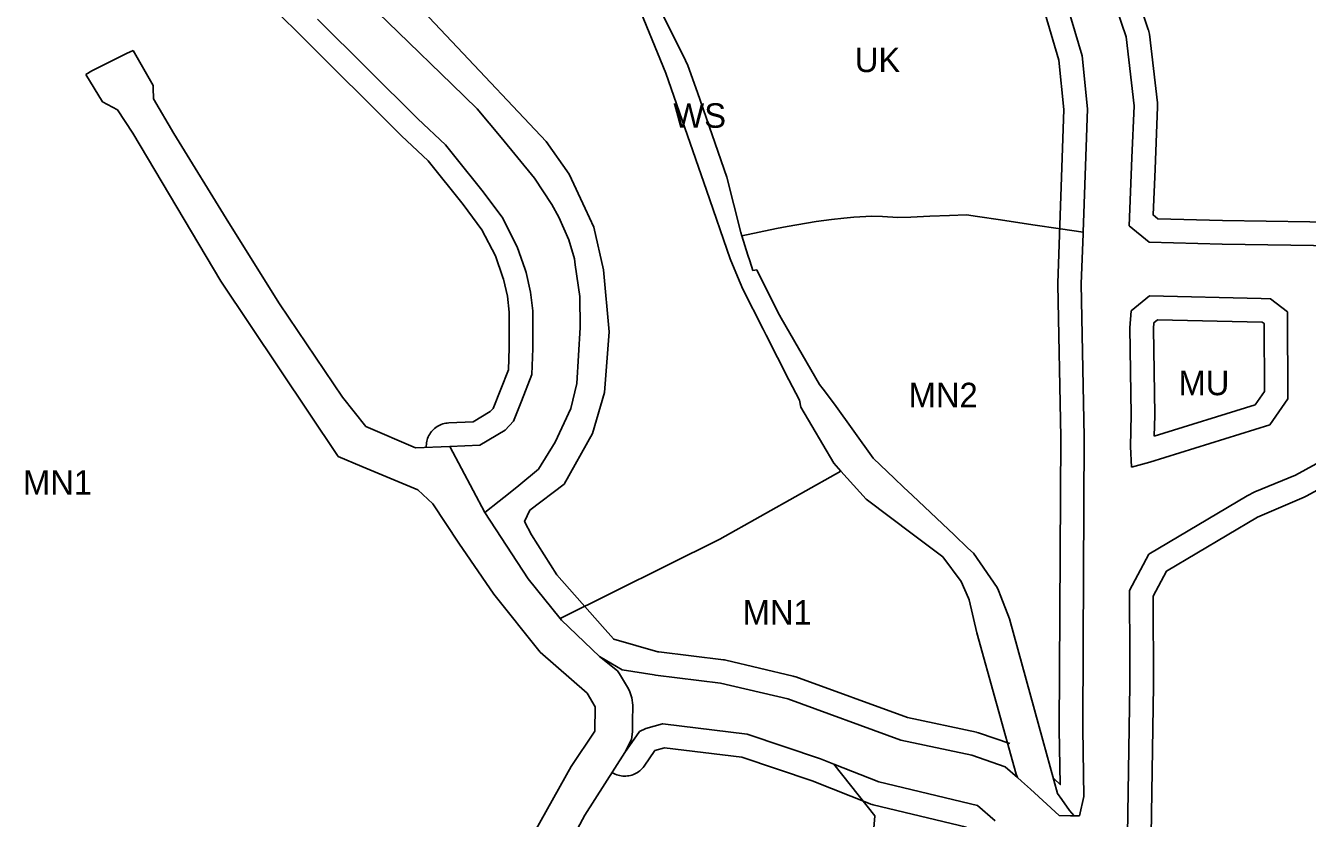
# Model space of a CAD drawing. Extents: x 7435758 to 7439981, y 5550649 to 5554049.
# Drawn here: x 7437108.7 to 7437381.1, y 5551668.8 to 5551837.1 of the extents above; entities that cross this region are included whole.
import ezdxf

# ---------------------------------------------------------------- set-up
doc = ezdxf.new("R2010")
doc.units = 0
for name, color, linetype in [('linie_rozgraniczające', 7, 'Continuous'), ('linie_zabudowy_nieprzekraczalne', 7, 'Continuous'), ('oznaczenia_przeznaczen', 7, 'Continuous')]:
    doc.layers.add(name, color=color, linetype=linetype)

msp = doc.modelspace()

# ---------------------------------------------------------------- linework, layer by layer
at = {"layer": 'linie_rozgraniczające'}
for p, q in [((7437342.53, 5551834.72), (7437337.64, 5551849.43)), ((7437238.33, 5551842.82), (7437244.76, 5551827.03)), ((7437248.93, 5551829.73), (7437241.63, 5551844.38)), ((7437187.89, 5551835.71), (7437181.49, 5551841.92)), ((7437330.07, 5551841.21), (7437333.2, 5551830.73)), ((7437170.79, 5551838.52), (7437192.04, 5551817.35)), ((7437199.27, 5551824.66), (7437187.89, 5551835.71)), ((7437344.25, 5551820.11), (7437342.53, 5551834.72)), ((7437130.2, 5551831.19), (7437122.83, 5551827.52)), ((7437131.58, 5551831.83), (7437130.2, 5551831.19)), ((7437135.84, 5551824.4), (7437131.58, 5551831.83)), ((7437249.47, 5551828.65), (7437248.93, 5551829.73)), ((7437251.48, 5551822.89), (7437249.47, 5551828.65)), ((7437333.2, 5551830.73), (7437334.34, 5551819.48)), ((7437122.83, 5551827.52), (7437121.57, 5551826.75)), ((7437121.57, 5551826.75), (7437125.09, 5551820.97)), ((7437244.76, 5551827.03), (7437253.4, 5551802.16)), ((7437135.85, 5551823.92), (7437135.84, 5551824.4)), ((7437135.91, 5551821.54), (7437135.85, 5551823.92)), ((7437204.65, 5551819.43), (7437199.27, 5551824.66)), ((7437125.09, 5551820.97), (7437128.27, 5551819.24)), ((7437140.23, 5551814.22), (7437135.91, 5551821.54)), ((7437257.73, 5551804.97), (7437251.48, 5551822.89)), ((7437128.27, 5551819.24), (7437131.54, 5551814.26)), ((7437209.79, 5551813.35), (7437204.65, 5551819.43)), ((7437334.34, 5551819.48), (7437333.98, 5551809.36)), ((7437343.79, 5551809.08), (7437344.25, 5551820.11)), ((7437192.04, 5551817.35), (7437197.92, 5551811.81)), ((7437131.54, 5551814.26), (7437150.19, 5551782.86)), ((7437151.89, 5551795.25), (7437140.23, 5551814.22)), ((7437216.85, 5551804.72), (7437209.79, 5551813.35)), ((7437197.92, 5551811.81), (7437200.23, 5551808.94)), ((7437333.98, 5551809.36), (7437333.41, 5551793.26)), ((7437200.23, 5551808.94), (7437205.65, 5551802.2)), ((7437343.19, 5551794.6), (7437343.79, 5551809.08)), ((7437220.51, 5551799.11), (7437216.85, 5551804.72)), ((7437260.73, 5551793.18), (7437257.73, 5551804.97)), ((7437205.65, 5551802.2), (7437209.96, 5551796.43)), ((7437253.4, 5551802.16), (7437258.46, 5551787.58)), ((7437222.04, 5551796.45), (7437220.51, 5551799.11)), ((7437209.96, 5551796.43), (7437213.16, 5551790.18)), ((7437224.17, 5551791.6), (7437222.04, 5551796.45)), ((7437279.95, 5551795.97), (7437276.72, 5551795.5)), ((7437282.57, 5551796.22), (7437279.95, 5551795.97)), ((7437284.72, 5551796.42), (7437282.57, 5551796.22)), ((7437288.52, 5551796.69), (7437284.72, 5551796.42)), ((7437290.81, 5551796.62), (7437288.52, 5551796.69)), ((7437294.07, 5551796.37), (7437290.81, 5551796.62)), ((7437296.8, 5551796.48), (7437294.07, 5551796.37)), ((7437300.84, 5551796.65), (7437296.8, 5551796.48)), ((7437305.05, 5551796.82), (7437300.84, 5551796.65)), ((7437308.64, 5551796.97), (7437305.05, 5551796.82)), ((7437311.01, 5551796.61), (7437308.64, 5551796.97)), ((7437315.87, 5551795.89), (7437311.01, 5551796.61)), ((7437322.76, 5551794.85), (7437315.87, 5551795.89)), ((7437162.7, 5551778.05), (7437151.89, 5551795.25)), ((7437260.91, 5551792.5), (7437260.73, 5551793.18)), ((7437268.28, 5551794.06), (7437260.91, 5551792.5)), ((7437270.56, 5551794.45), (7437268.28, 5551794.06)), ((7437276.72, 5551795.5), (7437270.56, 5551794.45)), ((7437328.64, 5551793.97), (7437322.76, 5551794.85)), ((7437333.41, 5551793.26), (7437328.64, 5551793.97)), ((7437333.41, 5551793.26), (7437333.4, 5551792.92)), ((7437347.45, 5551791.15), (7437343.19, 5551794.6)), ((7437225.33, 5551787.62), (7437224.17, 5551791.6)), ((7437262.2, 5551788.39), (7437260.91, 5551792.5)), ((7437333.4, 5551792.92), (7437333.02, 5551782.27)), ((7437362.95, 5551790.73), (7437347.45, 5551791.15)), ((7437391.92, 5551790.26), (7437362.95, 5551790.73)), ((7437213.16, 5551790.18), (7437214.87, 5551785.32)), ((7437225.51, 5551786.35), (7437225.33, 5551787.62)), ((7437258.46, 5551787.58), (7437260.02, 5551783.82)), ((7437262.58, 5551787.16), (7437262.2, 5551788.39)), ((7437214.87, 5551785.32), (7437215.1, 5551784.68)), ((7437226.5, 5551779.6), (7437225.51, 5551786.35)), ((7437263.23, 5551785.09), (7437262.58, 5551787.16)), ((7437264.08, 5551785.25), (7437263.23, 5551785.09)), ((7437268.65, 5551776.1), (7437264.08, 5551785.25)), ((7437150.19, 5551782.86), (7437175.17, 5551745.63)), ((7437215.1, 5551784.68), (7437216.03, 5551780.49)), ((7437260.02, 5551783.82), (7437261.13, 5551781.16)), ((7437333.02, 5551782.27), (7437333.66, 5551749.77)), ((7437216.03, 5551780.49), (7437216.48, 5551776.54)), ((7437226.57, 5551772.99), (7437226.5, 5551779.6)), ((7437261.13, 5551781.16), (7437265.41, 5551772.68)), ((7437343.65, 5551776.57), (7437347.49, 5551779.72)), ((7437347.49, 5551779.72), (7437371.21, 5551779.19)), ((7437176.08, 5551758.24), (7437162.7, 5551778.05)), ((7437371.21, 5551779.19), (7437373.26, 5551779.12)), ((7437373.26, 5551779.12), (7437376.85, 5551776.36)), ((7437216.48, 5551776.54), (7437216.48, 5551768.59)), ((7437268.92, 5551775.64), (7437268.65, 5551776.1)), ((7437269.29, 5551774.98), (7437268.92, 5551775.64)), ((7437277.44, 5551760.89), (7437269.29, 5551774.98)), ((7437343.34, 5551772.98), (7437343.65, 5551776.57)), ((7437376.85, 5551776.36), (7437376.93, 5551757.87)), ((7437225.88, 5551761.1), (7437226.57, 5551772.99)), ((7437265.41, 5551772.68), (7437266.06, 5551771.41)), ((7437266.06, 5551771.41), (7437270.88, 5551761.88)), ((7437343.64, 5551754.47), (7437343.34, 5551772.98)), ((7437216.48, 5551768.59), (7437216.29, 5551763.03)), ((7437216.29, 5551763.03), (7437214.07, 5551757.39)), ((7437224.57, 5551755.83), (7437225.88, 5551761.1)), ((7437270.88, 5551761.88), (7437273.13, 5551757.57)), ((7437278.17, 5551759.94), (7437277.44, 5551760.89)), ((7437181, 5551751.96), (7437176.08, 5551758.24)), ((7437280.58, 5551756.75), (7437278.17, 5551759.94)), ((7437376.93, 5551757.87), (7437373.07, 5551752.36)), ((7437214.07, 5551757.39), (7437212.38, 5551753.1)), ((7437221.24, 5551748.69), (7437224.57, 5551755.83)), ((7437273.13, 5551757.57), (7437273.42, 5551756.12)), ((7437273.42, 5551756.12), (7437280.47, 5551744.21)), ((7437288.8, 5551745.24), (7437280.58, 5551756.75)), ((7437212.38, 5551753.1), (7437210.63, 5551751.22)), ((7437343.5, 5551747.76), (7437343.64, 5551754.47)), ((7437373.07, 5551752.36), (7437347.6, 5551744.41)), ((7437191.56, 5551747.46), (7437181, 5551751.96)), ((7437210.63, 5551751.22), (7437205.28, 5551748.01)), ((7437333.66, 5551749.77), (7437333.45, 5551705.87)), ((7437198.86, 5551747.75), (7437191.56, 5551747.46)), ((7437205.28, 5551748.01), (7437198.86, 5551747.75)), ((7437198.86, 5551747.75), (7437206.28, 5551733.7)), ((7437205.28, 5551748.01), (7437205.28, 5551748.01)), ((7437205.28, 5551748.01), (7437205.28, 5551748.01)), ((7437217.69, 5551742.95), (7437221.24, 5551748.69)), ((7437343.71, 5551743.35), (7437343.5, 5551747.76)), ((7437175.17, 5551745.63), (7437180.18, 5551743.49)), ((7437280.47, 5551744.21), (7437281.97, 5551742.54)), ((7437293.36, 5551740.92), (7437288.8, 5551745.24)), ((7437347.6, 5551744.41), (7437343.71, 5551743.35)), ((7437378.55, 5551741.64), (7437382.91, 5551744.04)), ((7437180.18, 5551743.49), (7437192.05, 5551738.53)), ((7437213.5, 5551739.48), (7437217.69, 5551742.95)), ((7437256.26, 5551728.09), (7437281.97, 5551742.54)), ((7437281.97, 5551742.54), (7437287.32, 5551736.59)), ((7437369.87, 5551738.15), (7437378.55, 5551741.64)), ((7437211.34, 5551737.73), (7437213.5, 5551739.48)), ((7437295.25, 5551739.13), (7437293.36, 5551740.92)), ((7437297.16, 5551737.33), (7437295.25, 5551739.13)), ((7437192.05, 5551738.53), (7437195.28, 5551735.55)), ((7437206.28, 5551733.7), (7437209.36, 5551736.12)), ((7437209.36, 5551736.12), (7437211.34, 5551737.73)), ((7437287.32, 5551736.59), (7437297.41, 5551729.02)), ((7437303.53, 5551731.3), (7437297.16, 5551737.33)), ((7437347.38, 5551724.87), (7437368.28, 5551737.25)), ((7437368.28, 5551737.25), (7437369.87, 5551738.15)), ((7437195.28, 5551735.55), (7437200.81, 5551727.22)), ((7437206.28, 5551733.7), (7437215.51, 5551719.65)), ((7437306, 5551728.97), (7437303.53, 5551731.3)), ((7437222.33, 5551711.2), (7437256.26, 5551728.09)), ((7437297.41, 5551729.02), (7437303.64, 5551724.33)), ((7437308.95, 5551726.17), (7437306, 5551728.97)), ((7437200.81, 5551727.22), (7437208.25, 5551716.37)), ((7437310.1, 5551725.09), (7437308.95, 5551726.17)), ((7437315.18, 5551717.81), (7437310.1, 5551725.09)), ((7437303.64, 5551724.33), (7437307.51, 5551719.07)), ((7437343.26, 5551717.18), (7437347.38, 5551724.87)), ((7437215.51, 5551719.65), (7437222.33, 5551711.2)), ((7437307.51, 5551719.07), (7437309.08, 5551715.51)), ((7437315.44, 5551717.16), (7437315.18, 5551717.81)), ((7437315.94, 5551715.86), (7437315.44, 5551717.16)), ((7437343.34, 5551702.98), (7437343.26, 5551717.18)), ((7437208.25, 5551716.37), (7437218.08, 5551704.06)), ((7437309.08, 5551715.51), (7437309.23, 5551715.18)), ((7437309.23, 5551715.18), (7437310.86, 5551708.2)), ((7437317.77, 5551711.13), (7437315.94, 5551715.86)), ((7437222.6, 5551710.86), (7437222.33, 5551711.2)), ((7437230.7, 5551703.15), (7437222.6, 5551710.86)), ((7437324.84, 5551685.4), (7437317.77, 5551711.13)), ((7437310.86, 5551708.2), (7437319.17, 5551678.19)), ((7437333.45, 5551705.87), (7437333.36, 5551687.76)), ((7437218.08, 5551704.06), (7437228.03, 5551695.39)), ((7437230.7, 5551703.15), (7437234.49, 5551700.1)), ((7437235.52, 5551700.32), (7437230.7, 5551703.15)), ((7437343.37, 5551696.97), (7437343.34, 5551702.98)), ((7437234.49, 5551700.1), (7437234.89, 5551699.5)), ((7437234.89, 5551699.5), (7437236.62, 5551696.62)), ((7437242.31, 5551699.24), (7437235.52, 5551700.32)), ((7437242.54, 5551699.2), (7437242.31, 5551699.24)), ((7437256.39, 5551697.51), (7437242.54, 5551699.2)), ((7437228.03, 5551695.39), (7437229.76, 5551692.5)), ((7437236.62, 5551696.62), (7437237.02, 5551695.86)), ((7437237.02, 5551695.86), (7437237.53, 5551694.38)), ((7437270.65, 5551694.13), (7437256.39, 5551697.51)), ((7437342.85, 5551665.33), (7437343.37, 5551696.97)), ((7437229.76, 5551692.5), (7437229.66, 5551687.29)), ((7437237.53, 5551694.38), (7437237.75, 5551692.83)), ((7437237.76, 5551692.35), (7437237.71, 5551689.79)), ((7437237.75, 5551692.83), (7437237.76, 5551692.35)), ((7437294.72, 5551685.4), (7437270.65, 5551694.13)), ((7437237.71, 5551689.79), (7437237.66, 5551687.14)), ((7437229.66, 5551687.29), (7437224.64, 5551679.82)), ((7437236.06, 5551682.75), (7437239.19, 5551687.25)), ((7437237.66, 5551687.14), (7437237.47, 5551685.53)), ((7437239.19, 5551687.25), (7437240.52, 5551687.83)), ((7437240.52, 5551687.83), (7437244.05, 5551688.87)), ((7437244.05, 5551688.87), (7437244.09, 5551688.88)), ((7437244.09, 5551688.88), (7437262.03, 5551686.67)), ((7437333.36, 5551687.76), (7437333.6, 5551673.42)), ((7437237.47, 5551685.53), (7437236.06, 5551682.75)), ((7437262.03, 5551686.67), (7437277.6, 5551681.43)), ((7437309.75, 5551682.17), (7437294.72, 5551685.4)), ((7437327.95, 5551674.09), (7437324.84, 5551685.4)), ((7437227.53, 5551669.44), (7437236.06, 5551682.75)), ((7437277.6, 5551681.43), (7437280.43, 5551680.31)), ((7437316.85, 5551679.75), (7437309.75, 5551682.17)), ((7437224.64, 5551679.82), (7437216.9, 5551666.02)), ((7437280.43, 5551680.31), (7437289.18, 5551669.33)), ((7437280.43, 5551680.31), (7437289.99, 5551676.51)), ((7437319.46, 5551677.45), (7437316.85, 5551679.75)), ((7437289.99, 5551676.51), (7437310.98, 5551671.49)), ((7437319.17, 5551678.19), (7437319.46, 5551677.45)), ((7437319.46, 5551677.45), (7437320.36, 5551676.65)), ((7437320.36, 5551676.65), (7437322.24, 5551675)), ((7437322.24, 5551675), (7437328.34, 5551669.37)), ((7437328.86, 5551672.79), (7437327.95, 5551674.09)), ((7437333.6, 5551673.42), (7437332.64, 5551669.32)), ((7437310.98, 5551671.49), (7437314.72, 5551668.25)), ((7437330.51, 5551670.46), (7437328.86, 5551672.79)), ((7437223.43, 5551661.75), (7437227.53, 5551669.44)), ((7437289.18, 5551669.33), (7437288.76, 5551664.07)), ((7437328.34, 5551669.37), (7437330.77, 5551669.34)), ((7437331.52, 5551669.33), (7437330.51, 5551670.46)), ((7437330.77, 5551669.34), (7437331.52, 5551669.33)), ((7437332.64, 5551669.32), (7437331.52, 5551669.33))]:
    msp.add_line(p, q, dxfattribs=at)
at = {"layer": 'linie_zabudowy_nieprzekraczalne'}
for points in [[(7437327.25, 5551677.18), (7437328.56, 5551675.97), (7437328.36, 5551687.67), (7437328.36, 5551687.78), (7437328.66, 5551749.73), (7437328.02, 5551782.17), (7437328.02, 5551782.39), (7437328.03, 5551782.45), (7437329.33, 5551819.31), (7437328.28, 5551829.75), (7437325.32, 5551839.64), (7437310.51, 5551880.32), (7437291.66, 5551930.23), (7437291.66, 5551930.26), (7437278.98, 5551964.3), (7437278.97, 5551964.34), (7437266.89, 5551997.74), (7437262.43, 5551995.85), (7437262.4, 5551995.84), (7437197.61, 5551968.8)], [(7437315.57, 5551926.41), (7437332.15, 5551879.01), (7437332.17, 5551878.96), (7437342.33, 5551851.14), (7437342.38, 5551851), (7437347.27, 5551836.29), (7437347.3, 5551836.21), (7437347.39, 5551835.89), (7437347.45, 5551835.57), (7437347.49, 5551835.3), (7437349.21, 5551820.69), (7437349.22, 5551820.63), (7437349.24, 5551820.31), (7437349.25, 5551819.98), (7437349.24, 5551819.9), (7437348.7, 5551806.67), (7437348.29, 5551796.91), (7437349.28, 5551796.1), (7437363.06, 5551795.73), (7437390.83, 5551795.28)], [(7437165.17, 5551869.95), (7437199.31, 5551833.78), (7437219.36, 5551812.53), (7437224.19, 5551805.57), (7437227.61, 5551798.26), (7437229.46, 5551794.3), (7437231.53, 5551785.24), (7437232.7, 5551772.13), (7437231.76, 5551759.2), (7437229.18, 5551750.51), (7437223.17, 5551739.77), (7437215.85, 5551734.22), (7437214.76, 5551731.79), (7437216.25, 5551728.99), (7437221.59, 5551720.51), (7437231.29, 5551709.54), (7437233.64, 5551706.89), (7437233.73, 5551706.86), (7437243.09, 5551704.18), (7437243.24, 5551704.16), (7437257, 5551702.47), (7437257.17, 5551702.45), (7437257.49, 5551702.39), (7437257.54, 5551702.37), (7437271.8, 5551699), (7437272.06, 5551698.93), (7437272.35, 5551698.83), (7437296.1, 5551690.21), (7437310.8, 5551687.06), (7437310.85, 5551687.05), (7437311.17, 5551686.96), (7437311.37, 5551686.9), (7437317.83, 5551684.7)], [(7437193.86, 5551747.55), (7437193.86, 5551747.88), (7437193.88, 5551748.2), (7437193.92, 5551748.53), (7437193.98, 5551748.85), (7437194.06, 5551749.17), (7437194.16, 5551749.48), (7437194.29, 5551749.78), (7437194.43, 5551750.08), (7437194.59, 5551750.36), (7437194.77, 5551750.63), (7437194.97, 5551750.9), (7437195.18, 5551751.14), (7437195.41, 5551751.38), (7437195.65, 5551751.59), (7437195.91, 5551751.79), (7437196.18, 5551751.98), (7437196.47, 5551752.14), (7437196.76, 5551752.29), (7437197.06, 5551752.42), (7437197.37, 5551752.53), (7437197.68, 5551752.61), (7437198, 5551752.68), (7437198.33, 5551752.73), (7437198.65, 5551752.75), (7437203.81, 5551752.96), (7437207.45, 5551755.15), (7437208.08, 5551755.82), (7437211.32, 5551764.06), (7437211.48, 5551768.68), (7437211.48, 5551776.26), (7437211.09, 5551779.66), (7437210.28, 5551783.3), (7437210.15, 5551783.66), (7437208.55, 5551788.2), (7437205.7, 5551793.77), (7437201.7, 5551799.14), (7437194.24, 5551808.41), (7437188.61, 5551813.71), (7437188.51, 5551813.81), (7437167.28, 5551834.96), (7437162.39, 5551839.78)], [(7437348.54, 5551749.94), (7437369.95, 5551756.62), (7437371.93, 5551759.44), (7437371.86, 5551773.89), (7437371.49, 5551774.18), (7437349.23, 5551774.68), (7437348.45, 5551774.04), (7437348.34, 5551772.8), (7437348.64, 5551754.55), (7437348.64, 5551754.39), (7437348.64, 5551754.36), (7437348.54, 5551749.94)], [(7437346.28, 5551656.3), (7437347.77, 5551664.43), (7437347.79, 5551664.55), (7437347.83, 5551664.88), (7437347.85, 5551665.2), (7437347.85, 5551665.25), (7437348.37, 5551696.89), (7437348.37, 5551697), (7437348.27, 5551715.94), (7437351.13, 5551721.28), (7437370.43, 5551732.71), (7437380.41, 5551737), (7437380.65, 5551737.1), (7437380.94, 5551737.25), (7437380.97, 5551737.26), (7437385.32, 5551739.66)], [(7437308.63, 5551666.91), (7437288.83, 5551671.65), (7437288.58, 5551671.71), (7437288.27, 5551671.82), (7437288.15, 5551671.86), (7437275.88, 5551676.73), (7437260.91, 5551681.77), (7437244.51, 5551683.79), (7437242.45, 5551683.19), (7437240.17, 5551679.9), (7437240.15, 5551679.87), (7437239.95, 5551679.61), (7437239.74, 5551679.36), (7437239.51, 5551679.13), (7437239.26, 5551678.91), (7437239.01, 5551678.71), (7437238.73, 5551678.52), (7437238.45, 5551678.36), (7437238.16, 5551678.21), (7437237.86, 5551678.08), (7437237.55, 5551677.98), (7437237.24, 5551677.89), (7437236.91, 5551677.82), (7437236.59, 5551677.78), (7437236.26, 5551677.75), (7437235.94, 5551677.75), (7437235.61, 5551677.77), (7437235.29, 5551677.81), (7437234.96, 5551677.87), (7437234.65, 5551677.95), (7437234.34, 5551678.06), (7437234.03, 5551678.18), (7437233.74, 5551678.32), (7437233.45, 5551678.48), (7437233.36, 5551678.54)]]:
    msp.add_lwpolyline(points, dxfattribs=at)

# ---------------------------------------------------------------- texts
at = {"layer": 'oznaczenia_przeznaczen'}
for s, p in [('UK', (7437284.91, 5551827.25)), ('WS', (7437246.36, 5551815.43)), ('MU', (7437353.68, 5551758.64)), ('MN2', (7437296.34, 5551756.08)), ('MN1', (7437108.18, 5551737.52)), ('MN1', (7437261.08, 5551709.92))]:
    msp.add_text(s, height=5.2, dxfattribs=at).set_placement(p)

doc.saveas('drawing.dxf')
